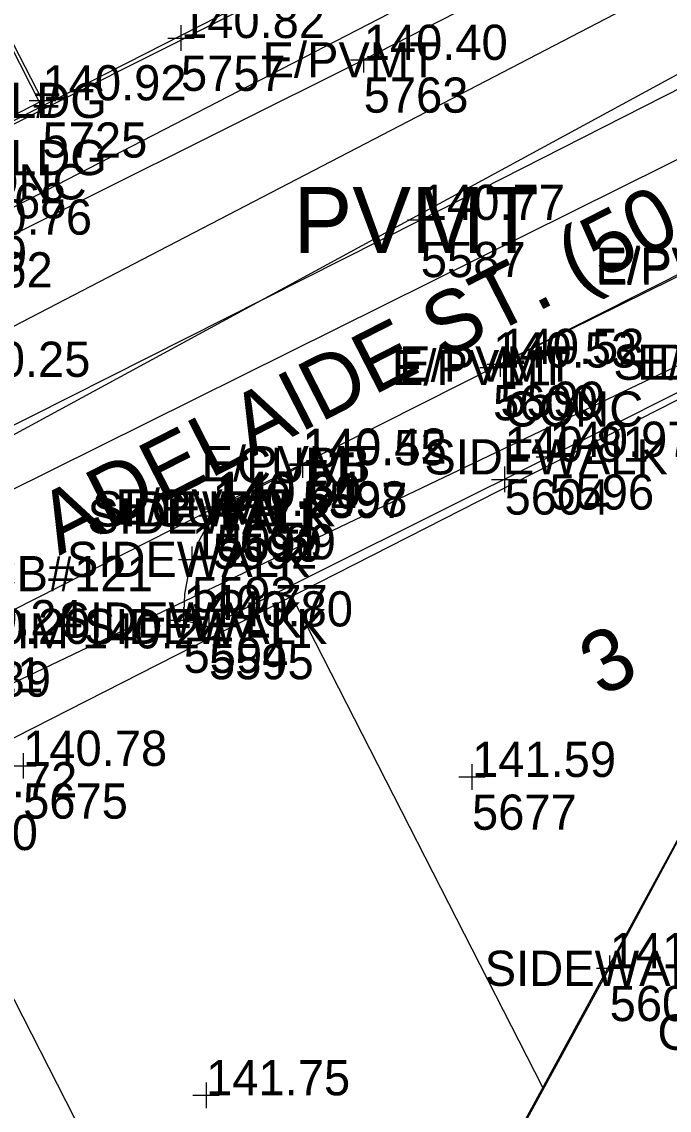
# Model space of a CAD drawing. Extents: x 13482495 to 13483389, y 311646 to 312209.
# Drawn here: x 13483186.7 to 13483245.5, y 311982.2 to 312081.1 of the extents above; entities that cross this region are included whole.
import ezdxf

# ---------------------------------------------------------------- set-up
doc = ezdxf.new("R2010")
doc.units = 0
for name, color, linetype in [('V-ANNO-TEXT', 7, 'Continuous'), ('V-BLDG-OTLN', 7, 'Continuous'), ('V-COMM-UNDR', 7, 'Continuous'), ('V-DOMW-MAIN', 7, 'Continuous'), ('V-ELEC-UNDR', 7, 'Continuous'), ('V-NGAS-MAIN', 7, 'Continuous'), ('V-PROP-IDEN', 7, 'Continuous'), ('V-PROP-LINE', 7, 'Continuous'), ('V-PROP-RWAY', 7, 'Continuous'), ('V-PVMT-CNTR', 7, 'Continuous'), ('V-PVMT-ROAD', 7, 'Continuous'), ('V-PVMT-SPOT', 7, 'Continuous'), ('V-SITE-IDEN', 7, 'Continuous'), ('V-SITE-SPOT', 7, 'Continuous'), ('V-SITE-WALK', 7, 'Continuous'), ('V-STRM-MAIN', 7, 'Continuous'), ('V-STRM-MHOL-IDEN', 7, 'Continuous'), ('V-SURV-PNTS', 7, 'Continuous'), ('V-TOPO-DRAN-SPOT', 7, 'Continuous'), ('V-TOPO-LINE-IDEN', 7, 'Continuous'), ('V-TOPO-SPOT', 7, 'Continuous'), ('V-UTIL-OVHD', 7, 'Continuous')]:
    doc.layers.add(name, color=color, linetype=linetype)

msp = doc.modelspace()

# ---------------------------------------------------------------- linework, layer by layer
at = {"layer": 'V-BLDG-OTLN'}
msp.add_lwpolyline([(13483167.593, 312063.142), (13483188.614, 312073.96), (13483178.694, 312093.211), (13483202.711, 312105.095), (13483208.311, 312094.215), (13483209.24, 312094.628), (13483197.432, 312118.302), (13483218.595, 312129.094), (13483235.983, 312138.003), (13483252.324, 312106.202), (13483284.232, 312122.552)], dxfattribs=at)
at = {"layer": 'V-COMM-UNDR'}
msp.add_lwpolyline([(13482638.43, 311773.216), (13482816.883, 311864.737), (13483031.639, 311973.194), (13483313.841, 312119.913)], dxfattribs=at)
at = {"layer": 'V-DOMW-MAIN'}
msp.add_lwpolyline([(13482679.686, 311784.595), (13482814.121, 311851.608), (13482868.23, 311877.786), (13483086.631, 311989.59), (13483299.889, 312105.497)], dxfattribs=at)
at = {"layer": 'V-ELEC-UNDR'}
msp.add_lwpolyline([(13483136.817, 311997.525), (13483275.634, 312063.845), (13483295.351, 312065.833)], dxfattribs=at)
at = {"layer": 'V-NGAS-MAIN'}
msp.add_lwpolyline([(13482633.573, 311784.98), (13482635.758, 311786.099), (13483013.716, 311979.941), (13483125.923, 312033.234), (13483152.951, 312055.23), (13483267.213, 312112.659)], dxfattribs=at)
at = {"layer": 'V-PROP-LINE'}
for p, q in [((13483144.303, 312160.044), (13483188.531, 312073.398)), ((13483234.046, 311984.23), (13483211.254, 312028.882)), ((13483211.388, 311942.551), (13483176.398, 312011.098))]:
    msp.add_line(p, q, dxfattribs=at)
at = {"layer": 'V-PROP-RWAY'}
for p, q in [((13482953.352, 311953.429), (13483318.617, 312139.792)), ((13482976.076, 311908.891), (13483276.388, 312062.114)), ((13483192.658, 311908.098), (13483276.388, 312062.114))]:
    msp.add_line(p, q, dxfattribs=at)
at = {"layer": 'V-PVMT-CNTR'}
msp.add_lwpolyline([(13482583.662, 311737.164), (13482615.839, 311753.602), (13482631.764, 311761.327), (13482644.15, 311768.11), (13482660.198, 311776.177), (13482708.876, 311801.215), (13482756.857, 311825.709), (13482802.864, 311849.141), (13482850.908, 311873.114), (13482897.465, 311897.251), (13482945.27, 311921.454), (13482988.058, 311943.315), (13483031.887, 311965.625), (13483078.612, 311989.652), (13483123.69, 312012.726), (13483173.425, 312038.092), (13483222.972, 312063.092), (13483269.032, 312086.568), (13483297.768, 312101.095)], dxfattribs=at)
at = {"layer": 'V-PVMT-ROAD'}
for points in [[(13483046.678, 311990.555), (13483079.211, 312006.888), (13483099.452, 312017.279), (13483114.671, 312025.287), (13483151.358, 312044.239), (13483167.233, 312052.433), (13483217.784, 312077.641), (13483241.711, 312089.928), (13483254.89, 312096.387), (13483267.926, 312103.062), (13483277.817, 312108.173), (13483290.977, 312115.044), (13483305.237, 312122.083), (13483309.354, 312124.167), (13483313.224, 312125.961), (13483313.468, 312125.194), (13483324.552, 312130.515), (13483328.35, 312132.225), (13483330.471, 312133.097), (13483331.734, 312133.829), (13483332.523, 312134.417), (13483333.988, 312135.742), (13483335.834, 312137.796), (13483336.653, 312138.925)], [(13483179.868, 312024.55), (13483204.425, 312037.004), (13483212.241, 312040.93), (13483230.197, 312049.992), (13483229.536, 312049.672), (13483248.024, 312058.978)], [(13483229.536, 312049.672), (13483248.062, 312058.819), (13483251.811, 312050.159)], [(13483204.461, 312036.826), (13483212.229, 312040.795)]]:
    msp.add_lwpolyline(points, dxfattribs=at)
at = {"layer": 'V-PVMT-SPOT'}
for p, q in [((13483217.784, 312078.801), (13483217.784, 312076.481)), ((13483216.584, 312077.641), (13483218.984, 312077.641)), ((13483222.972, 312064.252), (13483222.972, 312061.932)), ((13483221.772, 312063.092), (13483224.172, 312063.092)), ((13483229.536, 312050.832), (13483229.536, 312048.512)), ((13483229.536, 312050.832), (13483229.536, 312048.512)), ((13483230.197, 312051.152), (13483230.197, 312048.832)), ((13483228.336, 312049.672), (13483230.736, 312049.672)), ((13483228.336, 312049.672), (13483230.736, 312049.672)), ((13483228.997, 312049.992), (13483231.397, 312049.992)), ((13483234.648, 312042.715), (13483234.648, 312040.395)), ((13483212.229, 312041.955), (13483212.229, 312039.635)), ((13483212.241, 312042.09), (13483212.241, 312039.77)), ((13483233.448, 312041.555), (13483235.848, 312041.555)), ((13483211.029, 312040.795), (13483213.429, 312040.795)), ((13483211.041, 312040.93), (13483213.441, 312040.93)), ((13483204.425, 312038.164), (13483204.425, 312035.844)), ((13483204.461, 312037.986), (13483204.461, 312035.666)), ((13483204.461, 312037.986), (13483204.461, 312035.666)), ((13483203.225, 312037.004), (13483205.625, 312037.004)), ((13483203.261, 312036.826), (13483205.661, 312036.826)), ((13483203.261, 312036.826), (13483205.661, 312036.826)), ((13483204.058, 312037.337), (13483204.058, 312035.017)), ((13483202.858, 312036.177), (13483205.258, 312036.177)), ((13483202.179, 312033.395), (13483202.179, 312031.075)), ((13483200.979, 312032.235), (13483203.379, 312032.235)), ((13483201.423, 312027.876), (13483201.423, 312025.556)), ((13483201.423, 312027.876), (13483201.423, 312025.556)), ((13483200.223, 312026.716), (13483202.623, 312026.716)), ((13483200.223, 312026.716), (13483202.623, 312026.716)), ((13483203.729, 312027.294), (13483203.729, 312024.974)), ((13483202.529, 312026.134), (13483204.929, 312026.134)), ((13483240.127, 311996.222), (13483240.127, 311993.902)), ((13483238.927, 311995.062), (13483241.327, 311995.062))]:
    msp.add_line(p, q, dxfattribs=at)
at = {"layer": 'V-SITE-SPOT'}
for p, q in [((13483188.614, 312075.12), (13483188.614, 312072.8)), ((13483187.414, 312073.96), (13483189.814, 312073.96)), ((13483230.581, 312040.668), (13483230.581, 312038.348)), ((13483229.381, 312039.508), (13483231.781, 312039.508))]:
    msp.add_line(p, q, dxfattribs=at)
at = {"layer": 'V-SITE-WALK'}
for points in [[(13483219.99, 311958.205), (13483240.127, 311995.062), (13483265.094, 312041.637), (13483269.475, 312052.418), (13483267.261, 312057.854), (13483264.689, 312064.334), (13483265.367, 312065.469)], [(13483201.423, 312026.716), (13483203.729, 312026.134), (13483234.648, 312041.555), (13483251.811, 312050.159)], [(13483204.461, 312036.826), (13483204.058, 312036.177), (13483202.836, 312033.95), (13483201.979, 312031.559), (13483201.506, 312029.063), (13483201.423, 312026.716)]]:
    msp.add_lwpolyline(points, dxfattribs=at)
at = {"layer": 'V-STRM-MAIN'}
msp.add_lwpolyline([(13483018.553, 311955.79), (13483095.083, 311993.466), (13483335.462, 312112.939)], dxfattribs=at)
at = {"layer": 'V-TOPO-SPOT'}
for p, q in [((13483201.192, 312080.786), (13483201.192, 312078.466)), ((13483199.992, 312079.626), (13483202.392, 312079.626)), ((13483186.854, 312014.625), (13483186.854, 312012.305)), ((13483185.654, 312013.465), (13483188.054, 312013.465)), ((13483227.622, 312013.614), (13483227.622, 312011.294)), ((13483226.422, 312012.454), (13483228.822, 312012.454)), ((13483203.471, 311984.673), (13483203.471, 311982.353)), ((13483202.271, 311983.513), (13483204.671, 311983.513))]:
    msp.add_line(p, q, dxfattribs=at)
at = {"layer": 'V-UTIL-OVHD'}
msp.add_lwpolyline([(13483118.7, 312029.554), (13483287.396, 312116.623)], dxfattribs=at)

# ---------------------------------------------------------------- texts
at = {"layer": 'V-ANNO-TEXT'}
msp.add_text('ADELAIDE ST. (50 FT WD)', height=5.6, rotation=27.03125, dxfattribs=at).set_placement((13483190.121, 312032.547))
at = {"layer": 'V-PROP-IDEN'}
msp.add_text('3', height=5.6, rotation=27.03125, dxfattribs=at).set_placement((13483239.34, 312019.666))
at = {"layer": 'V-PVMT-SPOT'}
for s, p in [('140.40', (13483217.784, 312077.641)), ('140.77', (13483222.972, 312063.092)), ('140.53', (13483229.536, 312049.672)), ('140.53', (13483229.536, 312049.672)), ('140.52', (13483230.197, 312049.992)), ('140.97', (13483234.648, 312041.555)), ('140.55', (13483212.229, 312040.795)), ('140.42', (13483212.241, 312040.93)), ('140.34', (13483204.425, 312037.004)), ('140.60', (13483204.461, 312036.826)), ('140.60', (13483204.461, 312036.826)), ('140.54', (13483204.058, 312036.177)), ('140.69', (13483202.179, 312032.235)), ('140.77', (13483201.423, 312026.716)), ('140.77', (13483201.423, 312026.716)), ('140.80', (13483203.729, 312026.134)), ('140.20', (13483179.868, 312024.55)), ('141.67', (13483240.127, 311995.062))]:
    msp.add_text(s, height=3.2, dxfattribs=at).set_placement(p)
at = {"layer": 'V-SITE-IDEN'}
for p in [(13483180.027, 312064.954), (13483230.581, 312044.308)]:
    msp.add_text('CONC', height=3.2, dxfattribs=at).set_placement(p)
at = {"layer": 'V-SITE-SPOT'}
for s, p in [('140.92', (13483188.614, 312073.96)), ('140.76', (13483180.027, 312061.754)), ('140.81', (13483230.581, 312041.108)), ('140.72', (13483178.681, 312010.607))]:
    msp.add_text(s, height=3.2, dxfattribs=at).set_placement(p)
at = {"layer": 'V-STRM-MHOL-IDEN'}
for s, p in [('RIM 140.25', (13483170.846, 312048.826)), ('CB#121', (13483183.173, 312029.338)), ('RIM 140.24', (13483183.173, 312024.138))]:
    msp.add_text(s, height=3.2, dxfattribs=at).set_placement(p)
at = {"layer": 'V-SURV-PNTS'}
for s, p in [('5757', (13483201.192, 312074.826)), ('5763', (13483217.784, 312072.841)), ('5725', (13483188.614, 312068.76)), ('5759', (13483177.701, 312058.429)), ('5587', (13483222.972, 312057.892)), ('5762', (13483180.027, 312056.954)), ('5599', (13483230.197, 312045.192)), ('5600', (13483229.536, 312044.872)), ('5600', (13483229.536, 312044.872)), ('5604', (13483230.581, 312036.308)), ('5596', (13483234.648, 312036.755)), ('5597', (13483212.229, 312035.995)), ('5598', (13483212.241, 312036.13)), ('5592', (13483204.058, 312031.377)), ('5591', (13483204.425, 312032.204)), ('5590', (13483204.461, 312032.026)), ('5590', (13483204.461, 312032.026)), ('5593', (13483202.179, 312027.435)), ('5594', (13483201.423, 312021.916)), ('5594', (13483201.423, 312021.916)), ('5595', (13483203.729, 312021.334)), ('5821', (13483179.173, 312020.138)), ('5589', (13483179.868, 312019.75)), ('5675', (13483186.854, 312008.665)), ('5677', (13483227.622, 312007.654)), ('5580', (13483178.681, 312005.807)), ('5608', (13483240.127, 311990.262))]:
    msp.add_text(s, height=3.2, dxfattribs=at).set_placement(p)
at = {"layer": 'V-TOPO-DRAN-SPOT'}
msp.add_text('140.24', height=3.2, dxfattribs=at).set_placement((13483179.173, 312025.338))
at = {"layer": 'V-TOPO-LINE-IDEN'}
for s, height, p in [('E/PVMT', 3.2, (13483208.6, 312076.041)), ('BLDG', 3.2, (13483182.819, 312072.36)), ('#', 3.2, (13483187.796, 312072.36)), ('BLDG', 3.2, (13483182.819, 312067.16)), ('PVMT', 6, (13483211.397, 312060.092)), ('E/PVMT', 3.2, (13483238.84, 312057.378)), ('E/PVMT', 3.2, (13483238.878, 312057.219)), ('E/PVMT', 3.2, (13483220.352, 312048.072)), ('E/PVMT', 3.2, (13483220.352, 312048.072)), ('E/PVMT', 3.2, (13483221.013, 312048.392)), ('SIDEWALK', 3.2, (13483240.46, 312048.559)), ('E/PVMT', 3.2, (13483242.627, 312048.559)), ('E/PVMT', 3.2, (13483203.057, 312039.33)), ('SIDEWALK', 3.2, (13483223.298, 312039.955)), ('CURB', 3.2, (13483206.282, 312039.195)), ('E/PVMT', 3.2, (13483195.241, 312035.404)), ('SIDEWALK', 3.2, (13483192.707, 312034.577)), ('SIDEWALK', 3.2, (13483193.111, 312035.226)), ('CURB', 3.2, (13483198.515, 312035.226)), ('SIDEWALK', 3.2, (13483190.828, 312030.635)), ('SIDEWALK', 3.2, (13483190.072, 312025.116)), ('SIDEWALK', 3.2, (13483190.072, 312025.116)), ('SIDEWALK', 3.2, (13483192.378, 312024.534)), ('SIDEWALK', 3.2, (13483228.777, 311993.462)), ('GUTTER', 3.2, (13483244.467, 311987.652))]:
    msp.add_text(s, height=height, dxfattribs=at).set_placement(p)
at = {"layer": 'V-TOPO-SPOT'}
for s, p in [('140.82', (13483201.192, 312079.626)), ('140.68', (13483177.701, 312063.229)), ('140.78', (13483186.854, 312013.465)), ('141.59', (13483227.622, 312012.454)), ('141.75', (13483203.471, 311983.513))]:
    msp.add_text(s, height=3.2, dxfattribs=at).set_placement(p)

doc.saveas('drawing.dxf')
